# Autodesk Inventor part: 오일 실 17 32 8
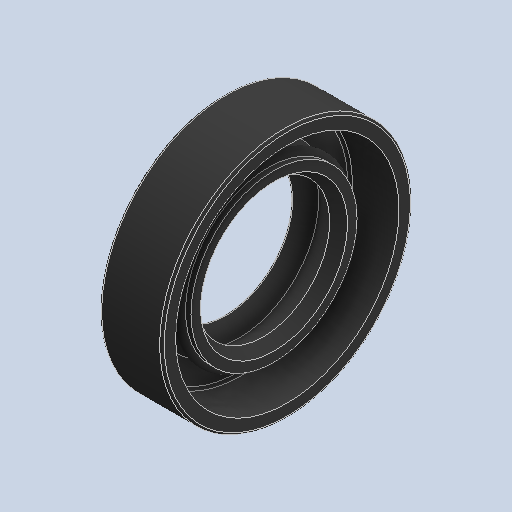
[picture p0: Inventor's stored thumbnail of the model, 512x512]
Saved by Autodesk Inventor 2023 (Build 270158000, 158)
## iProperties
Created: 2025-04
Part Number: 오일 실 17 32 8
Material: 고무
Description: 오일-실
Document SubType Name: Modeling
Designer: ADMIN_PC
Density: 0.93 g/cm^3
Appearance: 기본값
Author: jhkim
Revision Number: 1
Sending System: Autodesk Inventor 2026
Preprocessor: ST-DEVELOPER v20.1
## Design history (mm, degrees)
feature "Solid1"
node "솔리드1"
